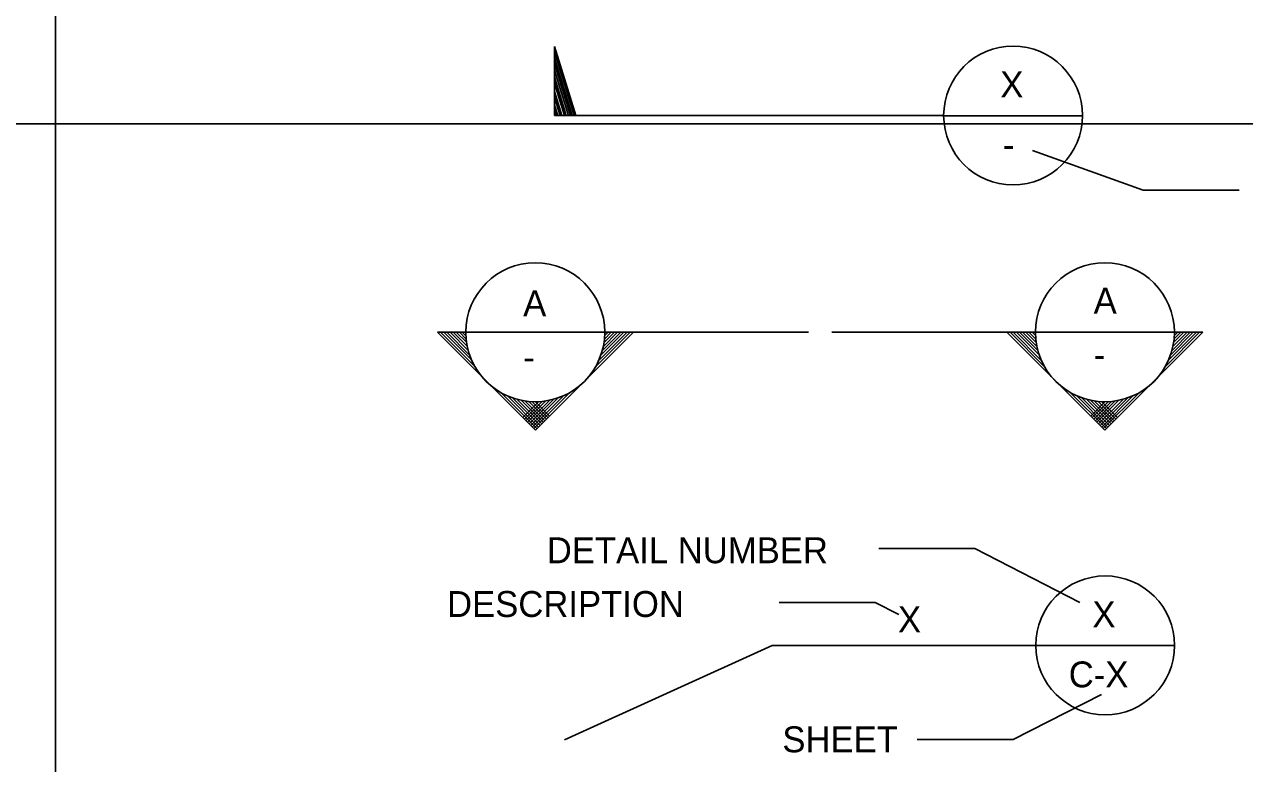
# Model space of a CAD drawing. Extents: x 6711682 to 6713077, y 1869209 to 1870525.
# Drawn here: x 6712021.9 to 6712351.4, y 1870100.2 to 1870299.7 of the extents above; entities that cross this region are included whole.
import ezdxf

# ---------------------------------------------------------------- set-up
doc = ezdxf.new("R2010")
doc.units = 0
for name, color, linetype in [('Control (1)', 7, 'Continuous'), ('G-TTLB-VIEW', 7, 'Continuous'), ('Sheet Format(10)', 7, 'Continuous')]:
    doc.layers.add(name, color=color, linetype=linetype)

msp = doc.modelspace()

# ---------------------------------------------------------------- linework, layer by layer
at = {"layer": 'Control (1)'}
for p, q in [((6712165.05, 1870275.14), (6712165.05, 1870293.75)), ((6712165.05, 1870293.75), (6712170.76, 1870275.14)), ((6712170.32, 1870275.14), (6712165.05, 1870292.32)), ((6712165.05, 1870290.61), (6712169.8, 1870275.14)), ((6712169.36, 1870275.14), (6712165.05, 1870289.21)), ((6712165.05, 1870287.36), (6712168.8, 1870275.14)), ((6712168.22, 1870275.14), (6712165.05, 1870285.48)), ((6712165.05, 1870283.87), (6712167.73, 1870275.14)), ((6712167.06, 1870275.14), (6712165.05, 1870281.67)), ((6712165.05, 1870280.05), (6712166.56, 1870275.14)), ((6712165.92, 1870275.14), (6712165.05, 1870277.97)), ((6712165.05, 1870276.42), (6712165.45, 1870275.14)), ((6712270.14, 1870275.14), (6712165.05, 1870275.14)), ((6712269.94, 1870275.09), (6712307.64, 1870275.09)), ((6712294.1, 1870265.71), (6712324.02, 1870254.95)), ((6712324.02, 1870254.95), (6712349.93, 1870254.95)), ((6712233.63, 1870216.63), (6712133.43, 1870216.63)), ((6712159.88, 1870190.19), (6712133.43, 1870216.63)), ((6712143.51, 1870207.4), (6712134.28, 1870216.63)), ((6712142.68, 1870209.08), (6712135.13, 1870216.63)), ((6712142.13, 1870210.48), (6712135.98, 1870216.63)), ((6712141.74, 1870211.72), (6712136.83, 1870216.63)), ((6712141.47, 1870212.84), (6712137.67, 1870216.63)), ((6712141.25, 1870213.91), (6712138.52, 1870216.63)), ((6712141.22, 1870214.79), (6712139.37, 1870216.63)), ((6712141.13, 1870215.65), (6712140.14, 1870216.63)), ((6712141.14, 1870215.71), (6712141.13, 1870215.73)), ((6712186.28, 1870216.59), (6712159.88, 1870190.19)), ((6712185.48, 1870216.63), (6712175.95, 1870207.11)), ((6712184.63, 1870216.63), (6712176.94, 1870208.95)), ((6712183.78, 1870216.63), (6712177.46, 1870210.32)), ((6712182.93, 1870216.63), (6712177.93, 1870211.64)), ((6712182.08, 1870216.63), (6712178.18, 1870212.73)), ((6712181.23, 1870216.63), (6712178.38, 1870213.78)), ((6712180.38, 1870216.63), (6712178.52, 1870214.77)), ((6712179.53, 1870216.63), (6712178.56, 1870215.66)), ((6712239.92, 1870216.63), (6712340.12, 1870216.63)), ((6712287.27, 1870216.59), (6712313.67, 1870190.19)), ((6712288.07, 1870216.63), (6712297.6, 1870207.11)), ((6712288.92, 1870216.63), (6712296.6, 1870208.95)), ((6712289.77, 1870216.63), (6712296.09, 1870210.32)), ((6712290.62, 1870216.63), (6712295.62, 1870211.64)), ((6712291.47, 1870216.63), (6712295.37, 1870212.73)), ((6712292.32, 1870216.63), (6712295.17, 1870213.78)), ((6712293.17, 1870216.63), (6712295.03, 1870214.77)), ((6712294.01, 1870216.63), (6712294.99, 1870215.66)), ((6712313.67, 1870190.19), (6712340.12, 1870216.63)), ((6712330.04, 1870207.4), (6712339.27, 1870216.63)), ((6712330.87, 1870209.08), (6712338.42, 1870216.63)), ((6712331.42, 1870210.48), (6712337.57, 1870216.63)), ((6712331.81, 1870211.72), (6712336.72, 1870216.63)), ((6712332.08, 1870212.84), (6712335.87, 1870216.63)), ((6712332.3, 1870213.91), (6712335.02, 1870216.63)), ((6712332.33, 1870214.79), (6712334.18, 1870216.63)), ((6712332.41, 1870215.71), (6712332.42, 1870215.73)), ((6712332.42, 1870215.65), (6712333.41, 1870216.63)), ((6712160.3, 1870190.61), (6712150.52, 1870200.39)), ((6712160.73, 1870191.04), (6712152.25, 1870199.51)), ((6712167.66, 1870199.67), (6712159.03, 1870191.04)), ((6712169.38, 1870200.54), (6712159.45, 1870190.61)), ((6712304.16, 1870200.54), (6712314.09, 1870190.61)), ((6712305.89, 1870199.67), (6712314.52, 1870191.04)), ((6712312.82, 1870191.04), (6712321.3, 1870199.51)), ((6712313.25, 1870190.61), (6712323.03, 1870200.39)), ((6712161.15, 1870191.46), (6712153.66, 1870198.96)), ((6712161.58, 1870191.88), (6712154.86, 1870198.6)), ((6712162, 1870192.31), (6712155.97, 1870198.34)), ((6712160.82, 1870197.92), (6712156.48, 1870193.58)), ((6712161.79, 1870198.04), (6712156.91, 1870193.16)), ((6712162.42, 1870192.73), (6712157.06, 1870198.1)), ((6712162.74, 1870198.14), (6712157.33, 1870192.73)), ((6712163.78, 1870198.33), (6712157.76, 1870192.31)), ((6712162.85, 1870193.16), (6712158.02, 1870197.98)), ((6712164.87, 1870198.58), (6712158.18, 1870191.88)), ((6712166.24, 1870199.09), (6712158.61, 1870191.46)), ((6712163.27, 1870193.58), (6712158.9, 1870197.95)), ((6712163.7, 1870194.01), (6712159.79, 1870197.91)), ((6712307.31, 1870199.09), (6712314.94, 1870191.46)), ((6712308.68, 1870198.58), (6712315.37, 1870191.88)), ((6712309.77, 1870198.33), (6712315.79, 1870192.31)), ((6712309.85, 1870194.01), (6712313.75, 1870197.91)), ((6712310.28, 1870193.58), (6712314.65, 1870197.95)), ((6712310.7, 1870193.16), (6712315.53, 1870197.98)), ((6712310.81, 1870198.14), (6712316.22, 1870192.73)), ((6712311.12, 1870192.73), (6712316.49, 1870198.1)), ((6712311.55, 1870192.31), (6712317.58, 1870198.34)), ((6712311.75, 1870198.04), (6712316.64, 1870193.16)), ((6712311.97, 1870191.88), (6712318.69, 1870198.6)), ((6712312.4, 1870191.46), (6712319.89, 1870198.96)), ((6712312.73, 1870197.92), (6712317.07, 1870193.58)), ((6712278.56, 1870158.2), (6712252.65, 1870158.2)), ((6712306.88, 1870143.68), (6712278.56, 1870158.2)), ((6712251.61, 1870143.68), (6712225.7, 1870143.68)), ((6712258.06, 1870140.42), (6712251.61, 1870143.68)), ((6712223.81, 1870132.08), (6712167.77, 1870106.56)), ((6712295.01, 1870132.08), (6712223.81, 1870132.08)), ((6712294.81, 1870132.03), (6712332.51, 1870132.03)), ((6712312.8, 1870118.85), (6712288.92, 1870106.71)), ((6712288.92, 1870106.71), (6712263.01, 1870106.71))]:
    msp.add_line(p, q, dxfattribs=at)
for centre, radius in [((6712288.89, 1870275.14), 18.75), ((6712159.86, 1870216.63), 18.76), ((6712313.69, 1870216.63), 18.76), ((6712313.76, 1870132.08), 18.75)]:
    msp.add_circle(centre, radius, dxfattribs=at)
at = {"layer": 'G-TTLB-VIEW'}
for points in [[(6712030.32, 1870524.68), (6712727.83, 1870524.68), (6712727.83, 1869964.67), (6712030.32, 1869964.67)], [(6711841.98, 1870272.86), (6712888.25, 1870272.86), (6712888.25, 1869432.85), (6711841.98, 1869432.85)]]:
    msp.add_lwpolyline(points, close=True, dxfattribs=at)

# ---------------------------------------------------------------- texts
at = {"layer": 'Sheet Format(10)'}
for s, p in [('X', (6712285.44, 1870280.04)), ('-', (6712286.13, 1870263.8)), ('A', (6712156.58, 1870220.95)), ('A', (6712310.65, 1870221.65)), ('-', (6712156.58, 1870206.44)), ('-', (6712310.65, 1870207.13)), ('DETAIL NUMBER', (6712162.96, 1870154.26)), ('DESCRIPTION', (6712136.02, 1870139.75)), ('X', (6712310.31, 1870136.98)), ('X', (6712257.8, 1870135.6)), ('C-X', (6712303.92, 1870120.74)), ('SHEET', (6712226.58, 1870103.21))]:
    msp.add_text(s, height=7, dxfattribs=at).set_placement(p)

doc.saveas('drawing.dxf')
